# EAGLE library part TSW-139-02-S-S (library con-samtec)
THROUGH-HOLE .025" SQ POST HEADER Source: Samtec TSW.pdf
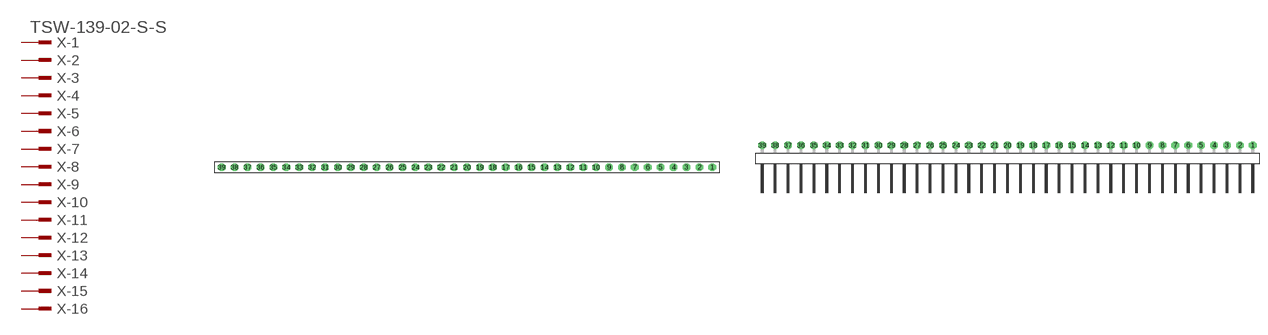
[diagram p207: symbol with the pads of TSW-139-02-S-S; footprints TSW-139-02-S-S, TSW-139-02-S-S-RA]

Designator prefix X; gates -1=MPINV -2=MPIN -3=MPIN -4=MPIN -5=MPIN -6=MPIN -7=MPIN -8=MPIN -9=MPIN -10=MPIN -11=MPIN -12=MPIN -13=MPIN -14=MPIN -15=MPIN -16=MPIN -17=MPIN -18=MPIN -19=MPIN -20=MPIN -21=MPIN -22=MPIN -23=MPIN -24=MPIN -25=MPIN -26=MPIN -27=MPIN -28=MPIN -29=MPIN -30=MPIN -31=MPIN -32=MPIN -33=MPIN -34=MPIN -35=MPIN -36=MPIN -37=MPIN -38=MPIN -39=MPIN

## TSW-139-02-S-S (OC_FARNELL: unknown; OC_NEWARK: unknown)  [TSW-139-02-S-S]
1  -1:1  pas
2  -2:1  pas
3  -3:1  pas
4  -4:1  pas
5  -5:1  pas
6  -6:1  pas
7  -7:1  pas
8  -8:1  pas
9  -9:1  pas
10  -10:1  pas
11  -11:1  pas
12  -12:1  pas
13  -13:1  pas
14  -14:1  pas
15  -15:1  pas
16  -16:1  pas
17  -17:1  pas
18  -18:1  pas
19  -19:1  pas
20  -20:1  pas
21  -21:1  pas
22  -22:1  pas
23  -23:1  pas
24  -24:1  pas
25  -25:1  pas
26  -26:1  pas
27  -27:1  pas
28  -28:1  pas
29  -29:1  pas
30  -30:1  pas
31  -31:1  pas
32  -32:1  pas
33  -33:1  pas
34  -34:1  pas
35  -35:1  pas
36  -36:1  pas
37  -37:1  pas
38  -38:1  pas
39  -39:1  pas

## TSW-139-02-S-S-RA (OC_FARNELL: unknown; OC_NEWARK: unknown)  [TSW-139-02-S-S-RA]
Pads as for TSW-139-02-S-S

## Footprint TSW-139-02-S-S (pad centres in mm)
THROUGH-HOLE .025" SQ POST HEADER Source: Samtec TSW.pdf
drill 1 pad 1.5 octagon: 1 48.26,0; 2 45.72,0; 3 43.18,0; 4 40.64,0; 5 38.1,0; 6 35.56,0; 7 33.02,0; 8 30.48,0; 9 27.94,0; 10 25.4,0; 11 22.86,0; 12 20.32,0; 13 17.78,0; 14 15.24,0; 15 12.7,0; 16 10.16,0; 17 7.62,0; 18 5.08,0; 19 2.54,0; 20 0,0; 21 -2.54,0; 22 -5.08,0; 23 -7.62,0; 24 -10.16,0; 25 -12.7,0; 26 -15.24,0; 27 -17.78,0; 28 -20.32,0; 29 -22.86,0; 30 -25.4,0; 31 -27.94,0; 32 -30.48,0; 33 -33.02,0; 34 -35.56,0; 35 -38.1,0; 36 -40.64,0; 37 -43.18,0; 38 -45.72,0; 39 -48.26,0

## Footprint TSW-139-02-S-S-RA (pad centres in mm)
THROUGH-HOLE .025" SQ POST HEADER Source: Samtec TSW.pdf
drill 1 pad 1.5 octagon: 1 48.26,1.524; 2 45.72,1.524; 3 43.18,1.524; 4 40.64,1.524; 5 38.1,1.524; 6 35.56,1.524; 7 33.02,1.524; 8 30.48,1.524; 9 27.94,1.524; 10 25.4,1.524; 11 22.86,1.524; 12 20.32,1.524; 13 17.78,1.524; 14 15.24,1.524; 15 12.7,1.524; 16 10.16,1.524; 17 7.62,1.524; 18 5.08,1.524; 19 2.54,1.524; 20 0,1.524; 21 -2.54,1.524; 22 -5.08,1.524; 23 -7.62,1.524; 24 -10.16,1.524; 25 -12.7,1.524; 26 -15.24,1.524; 27 -17.78,1.524; 28 -20.32,1.524; 29 -22.86,1.524; 30 -25.4,1.524; 31 -27.94,1.524; 32 -30.48,1.524; 33 -33.02,1.524; 34 -35.56,1.524; 35 -38.1,1.524; 36 -40.64,1.524; 37 -43.18,1.524; 38 -45.72,1.524; 39 -48.26,1.524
